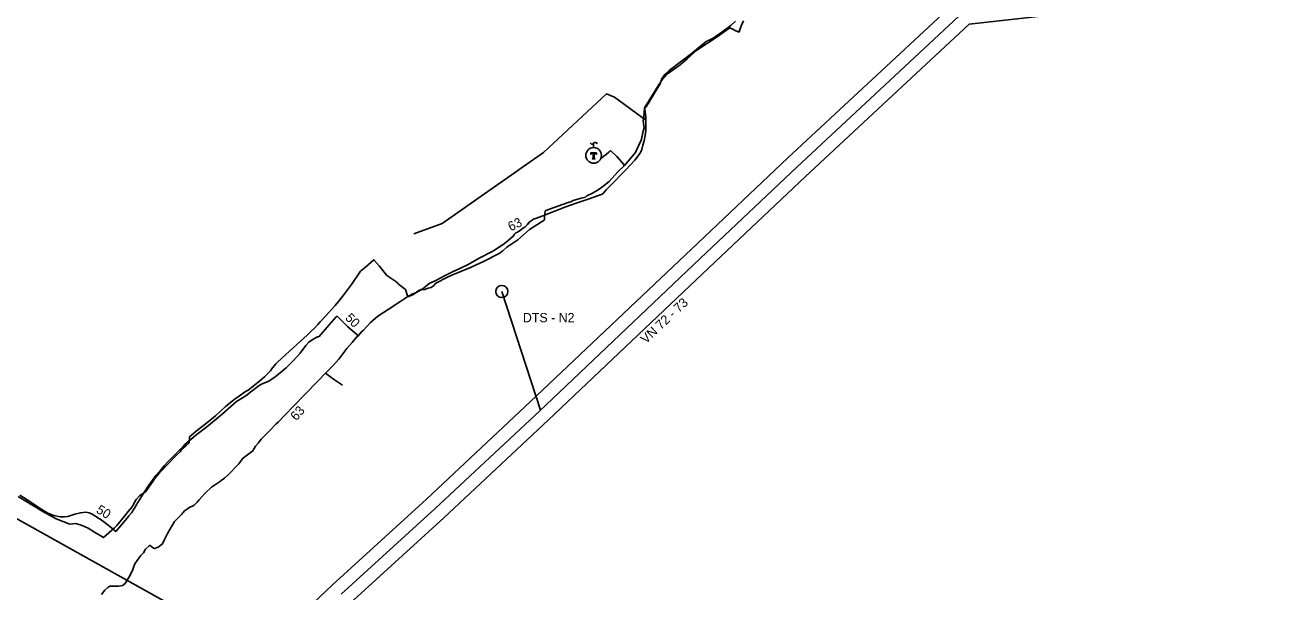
# Model space of a CAD drawing. Extents: x -545241 to -532622, y -1042837 to -1037240.
# Drawn here: x -543496 to -542416, y -1040596 to -1040106 of the extents above; entities that cross this region are included whole.
import ezdxf

# ---------------------------------------------------------------- set-up
doc = ezdxf.new("R2010")
doc.units = 0
for name, color, linetype in [('Vrstva 11', 7, 'Continuous'), ('Vrstva 16', 7, 'Continuous'), ('Vrstva 18', 7, 'Continuous'), ('Vrstva 29', 7, 'Continuous'), ('Vrstva 33', 7, 'Continuous'), ('Vrstva 35', 7, 'Continuous'), ('Vrstva 38', 7, 'Continuous'), ('Vrstva 57', 7, 'Continuous'), ('Vrstva 58', 7, 'Continuous'), ('Vrstva 59', 7, 'Continuous'), ('Vrstva 6', 7, 'Continuous')]:
    doc.layers.add(name, color=color, linetype=linetype)

# ---------------------------------------------------------------- blocks, each defined once
blk = doc.blocks.new('ETRAFN')
at = {"layer": 'Vrstva 6'}
blk.add_circle((0, 0), 7.5, dxfattribs=at)

msp = doc.modelspace()

# ---------------------------------------------------------------- linework, layer by layer
at = {"layer": 'Vrstva 11'}
msp.add_line((-543050.7, -1040438.8), (-543084.2, -1040336.3), dxfattribs=at)
at = {"layer": 'Vrstva 18'}
for points in [[(-542882.4, -1040102.9), (-542886.4, -1040106.6), (-542894.1, -1040112.3), (-542901.6, -1040117.6), (-542905.2, -1040119.3), (-542907.6, -1040120.2), (-542914, -1040125.4), (-542920.6, -1040131.1), (-542929.1, -1040137.3), (-542939.7, -1040145.3), (-542943.4, -1040148.8), (-542946.2, -1040152.9), (-542947.2, -1040156.2), (-542948, -1040157.9), (-542951.1, -1040162.9), (-542954.1, -1040167.9), (-542955.5, -1040170.2), (-542957.5, -1040173.6), (-542957.6, -1040173.7), (-542957.7, -1040173.9), (-542959.8, -1040177), (-542960.6, -1040178), (-542960.6, -1040178.6), (-542960.7, -1040179.1), (-542959.8, -1040185.4), (-542959.9, -1040197.5), (-542960.4, -1040201.5), (-542961.4, -1040206), (-542962.4, -1040209.9), (-542963.3, -1040213.5), (-542964.6, -1040216.9), (-542969.4, -1040222.7), (-542977.1, -1040231.2), (-542977.3, -1040231.4)], [(-542977.3, -1040231.4), (-542978.4, -1040232.5), (-542980.3, -1040234.4), (-542987.6, -1040241.8), (-542994.2, -1040248.5), (-542997.1, -1040251.8), (-542998.2, -1040252.4), (-543001.7, -1040253.7), (-543008.8, -1040256.2), (-543011.3, -1040257.2), (-543019.9, -1040260.1), (-543029.8, -1040263.3), (-543038.4, -1040266.9), (-543041.5, -1040267.9), (-543047.8, -1040270.6), (-543055.2, -1040273.2), (-543056.6, -1040273.5), (-543058, -1040274.6), (-543060.5, -1040276.5), (-543062.1, -1040278.5), (-543064.3, -1040280.7), (-543065, -1040281.1), (-543066.2, -1040281.9), (-543067.4, -1040282.8), (-543067.6, -1040282.9), (-543069.8, -1040284.5), (-543070.7, -1040284.9), (-543072.2, -1040285.7), (-543073.2, -1040286.8), (-543074.3, -1040288.5), (-543079.1, -1040292.4), (-543082.9, -1040295.7), (-543092, -1040301.5), (-543103.2, -1040307.3), (-543113.9, -1040313.3), (-543124.9, -1040318.4), (-543125, -1040318.5), (-543133, -1040322.4), (-543141.8, -1040327), (-543146.3, -1040329.1), (-543148.3, -1040330.4), (-543152.3, -1040333.9), (-543155.8, -1040335.9), (-543156.6, -1040336.4), (-543157.8, -1040337.2), (-543159.4, -1040337.7), (-543161.8, -1040338.7), (-543161.8, -1040338.7), (-543163.6, -1040339.6), (-543165.2, -1040340.5), (-543172.3, -1040345.1), (-543182.4, -1040351.7), (-543191.2, -1040357.6), (-543197.5, -1040363.1), (-543203.7, -1040369.6), (-543205, -1040370.8), (-543206.9, -1040372.8), (-543206.9, -1040372.9), (-543208.1, -1040374.6)], [(-543208.1, -1040374.6), (-543208.5, -1040374.2), (-543209.1, -1040373.9), (-543209.2, -1040373.8), (-543217.4, -1040366.5), (-543217.7, -1040366.2), (-543218, -1040366), (-543226.1, -1040357.9), (-543226.2, -1040357.8), (-543226.3, -1040357.7), (-543226.4, -1040357.7), (-543227.1, -1040358.2), (-543233.2, -1040365.1), (-543242.3, -1040375.5), (-543243.4, -1040375.4), (-543247.2, -1040377.5), (-543250.8, -1040380), (-543253.3, -1040383), (-543258.2, -1040389.4), (-543264.4, -1040396.2), (-543270.5, -1040402.1), (-543275.5, -1040406.6), (-543279.9, -1040410), (-543285.4, -1040413.7), (-543291.6, -1040416.4), (-543293.6, -1040417.5), (-543302, -1040423.8), (-543304.5, -1040425.8), (-543313.3, -1040431.4), (-543325.4, -1040441.9), (-543337.5, -1040452), (-543348.7, -1040460.7), (-543357.8, -1040468.5), (-543359.3, -1040470), (-543372.6, -1040483.4), (-543375.7, -1040486.8), (-543379.2, -1040491.1), (-543383.3, -1040495.6), (-543386.4, -1040500), (-543388.4, -1040502.8), (-543392.7, -1040509.3), (-543393.8, -1040511.1), (-543394.3, -1040512), (-543394.7, -1040512.5), (-543395.2, -1040513.3), (-543400.2, -1040521.3), (-543400.3, -1040521.5), (-543401.5, -1040523.5), (-543403.9, -1040527.3), (-543406.3, -1040530.1), (-543407.7, -1040531.9), (-543417.5, -1040543.6), (-543422.6, -1040539.2), (-543425.4, -1040536.8), (-543430, -1040533.4), (-543434.7, -1040530.5), (-543437.8, -1040528.7), (-543440.4, -1040527.5), (-543443.5, -1040526.9), (-543448.1, -1040527.4), (-543452.8, -1040528.7), (-543455.4, -1040529.5), (-543458.9, -1040530.5), (-543461.8, -1040530.9), (-543465.5, -1040531), (-543471, -1040529.6), (-543476.3, -1040527.6), (-543482.8, -1040523.7), (-543490.9, -1040518.3), (-543500.4, -1040512.1)], [(-543208.1, -1040374.6), (-543208.4, -1040375.1), (-543208.6, -1040375.2), (-543209.3, -1040375.3), (-543209.8, -1040375.8), (-543213.3, -1040380.4), (-543217.9, -1040385.5), (-543219.8, -1040387.8), (-543224.9, -1040394.7), (-543230.5, -1040400.7), (-543236.4, -1040406.7), (-543242.8, -1040413.5), (-543254.8, -1040425.8), (-543271.6, -1040443.2), (-543277.3, -1040449), (-543278.9, -1040450.6), (-543284.5, -1040456.4), (-543285, -1040457), (-543291.9, -1040463.9), (-543294.6, -1040467.2), (-543296.9, -1040469.8), (-543298.1, -1040471.8), (-543299.4, -1040474.2), (-543300.2, -1040474.8), (-543307.3, -1040479.8), (-543307.4, -1040479.9), (-543311.3, -1040485.2), (-543320.1, -1040494.2), (-543323.6, -1040497.6), (-543326.6, -1040499.6), (-543327.2, -1040500), (-543335, -1040505.3), (-543340.3, -1040510.4), (-543345.6, -1040516.1), (-543347.5, -1040518.5), (-543349.9, -1040520.7), (-543350.7, -1040521.5), (-543351.2, -1040521.6), (-543351.2, -1040521.6), (-543352.9, -1040522.3), (-543353.5, -1040522.6), (-543355.6, -1040523.9), (-543358.2, -1040525.8), (-543360.8, -1040528.9), (-543362.4, -1040530.6), (-543366.7, -1040535), (-543372.8, -1040545.4), (-543375.4, -1040550.4), (-543377.1, -1040554.1), (-543380.8, -1040557.1), (-543384, -1040558.3), (-543385, -1040558), (-543387.8, -1040555.6), (-543388.2, -1040555.5), (-543388.8, -1040555.9), (-543391.8, -1040558.8), (-543393.7, -1040561.9), (-543394, -1040562.2), (-543396.1, -1040564.6), (-543396.2, -1040564.7), (-543399.1, -1040568.6), (-543401.2, -1040571.4), (-543402, -1040573.7), (-543403.1, -1040577.3), (-543405.9, -1040582.6), (-543409.3, -1040588.4), (-543410.5, -1040589.3), (-543411, -1040589.7), (-543411.7, -1040590.2), (-543415.2, -1040590.7), (-543418.4, -1040590.9), (-543422.7, -1040590.8), (-543424.4, -1040592), (-543426.9, -1040594.3), (-543429.9, -1040598)], [(-543236.4, -1040406.7), (-543229.5, -1040411.9), (-543221.8, -1040417.1)]]:
    msp.add_lwpolyline(points, dxfattribs=at)
at = {"layer": 'Vrstva 33'}
for points in [[(-543215.4, -1040605.8), (-543134.2, -1040531.6), (-543044.2, -1040447.5), (-542905.4, -1040315.7), (-542822, -1040236.9), (-542680.6, -1040105.3), (-542572.1, -1040093.3), (-542432.8, -1040080.8), (-542229.9, -1040058.3), (-542111, -1040051.2), (-541878.9, -1039938), (-541766.7, -1039884.9)], [(-542699.6, -1040093), (-542837.1, -1040220.9), (-542920.5, -1040299.7), (-543059.3, -1040431.4), (-543149.1, -1040515.5), (-543230.4, -1040589.7), (-543402.9, -1040753.1), (-543445.3, -1040766.3)]]:
    msp.add_lwpolyline(points, dxfattribs=at)
at = {"layer": 'Vrstva 35'}
msp.add_lwpolyline([(-542959.7, -1040188.3), (-542987, -1040168.4), (-542993.8, -1040165.6), (-543048.3, -1040216.1), (-543135.7, -1040277.5), (-543160.2, -1040286.6)], dxfattribs=at)
at = {"layer": 'Vrstva 38'}
msp.add_lwpolyline([(-541771.3, -1039874.9), (-541883.7, -1039928.1), (-542113.9, -1040040.3), (-542230.8, -1040047.3), (-542433.9, -1040069.9), (-542573.2, -1040082.4), (-542685.4, -1040094.8), (-542829.5, -1040228.9), (-542913, -1040307.7), (-543051.7, -1040439.5), (-543141.7, -1040523.6), (-543222.9, -1040597.8)], dxfattribs=at)
at = {"layer": 'Vrstva 57'}
for p, q in [((-543004.9, -1040208.2), (-543004.9, -1040212)), ((-543007, -1040217.5), (-543007.4, -1040217.2)), ((-543006.7, -1040217.2), (-543007.3, -1040216.6)), ((-543006.3, -1040216.8), (-543006.7, -1040216.5)), ((-543005.6, -1040216.8), (-543005.9, -1040216.5)), ((-543005.7, -1040221.7), (-543005.9, -1040221.5)), ((-543005, -1040221.7), (-543005.5, -1040221.2)), ((-543004.5, -1040217.3), (-543005.2, -1040216.5)), ((-543004.5, -1040218), (-543005.2, -1040217.2)), ((-543004.5, -1040218.7), (-543005.2, -1040217.9)), ((-543004.5, -1040219.4), (-543005.2, -1040218.6)), ((-543004.5, -1040220.1), (-543005.2, -1040219.4)), ((-543004.5, -1040220.8), (-543005.2, -1040220.1)), ((-543004.2, -1040221.7), (-543005.2, -1040220.8)), ((-543004.2, -1040216.8), (-543004.5, -1040216.5)), ((-543003.5, -1040216.8), (-543003.8, -1040216.5)), ((-543002.3, -1040217.3), (-543003.1, -1040216.5)), ((-543002.4, -1040216.5), (-543002.5, -1040216.4))]:
    msp.add_line(p, q, dxfattribs=at)
msp.add_lwpolyline([(-543007.8, -1040207.8), (-543007.3, -1040208.4), (-543006.7, -1040208.9), (-543006.3, -1040209), (-543005.9, -1040209), (-543005.4, -1040208.7), (-543004.9, -1040208.2), (-543004.5, -1040207.8), (-543004, -1040207.5), (-543003.6, -1040207.4), (-543003.2, -1040207.5), (-543002.5, -1040208), (-543002, -1040208.7)], dxfattribs=at)
msp.add_lwpolyline([(-543002.4, -1040216.4), (-543002.3, -1040217.8), (-543002.5, -1040217.8), (-543003.3, -1040216.8), (-543004.5, -1040216.8), (-543004.5, -1040220.9), (-543003.7, -1040221.6), (-543003.7, -1040221.7), (-543006, -1040221.7), (-543006, -1040221.6), (-543005.2, -1040220.9), (-543005.2, -1040216.8), (-543006.3, -1040216.8), (-543007.2, -1040217.8), (-543007.4, -1040217.8), (-543007.3, -1040216.4), (-543007.1, -1040216.4), (-543006.8, -1040216.5), (-543002.9, -1040216.5), (-543002.6, -1040216.4)], close=True, dxfattribs=at)
msp.add_circle((-543004.9, -1040218.7), 6.75, dxfattribs=at)
at = {"layer": 'Vrstva 58'}
for points in [[(-542875.6, -1040102.6), (-542877.3, -1040106.3), (-542879.1, -1040111.6), (-542878.9, -1040111.9), (-542880.2, -1040112.1), (-542883.3, -1040110.5), (-542884.2, -1040110), (-542887.3, -1040108.6), (-542888.5, -1040109.4), (-542889.8, -1040110.4), (-542897.4, -1040115.8), (-542915.8, -1040127.8), (-542924.1, -1040135.2), (-542930.3, -1040140.5), (-542942.1, -1040148.8), (-542945.5, -1040152.9), (-542948, -1040156.8), (-542948.3, -1040157.3), (-542951.5, -1040162.3), (-542956.7, -1040170.8), (-542961.1, -1040177.7), (-542961.7, -1040185.9), (-542962.2, -1040188.7), (-542961.8, -1040191.3), (-542961.2, -1040195), (-542962.4, -1040198.9), (-542963.1, -1040202.1), (-542963.2, -1040202.7), (-542963.4, -1040203.4), (-542963.8, -1040205.6), (-542968.2, -1040214.7), (-542968.8, -1040216.1), (-542978.2, -1040227.3)], [(-542978.2, -1040227.3), (-542978.7, -1040227.3), (-542978.8, -1040226.8), (-542979.2, -1040226.3), (-542980.8, -1040224.4), (-542985, -1040219.6), (-542990.1, -1040214.7), (-542990.5, -1040214.9), (-542991.9, -1040216), (-542993.8, -1040217.6), (-542998.7, -1040221.4)], [(-542978.2, -1040227.3), (-542983.9, -1040232.8), (-542991.6, -1040241.3), (-542996.9, -1040245.6), (-543001, -1040248.5), (-543005.8, -1040251.2), (-543010.7, -1040253.5), (-543011.8, -1040254.7), (-543015.7, -1040255.6), (-543022.6, -1040257.6), (-543024.7, -1040258.9), (-543025.9, -1040259.2), (-543031.7, -1040261), (-543046.2, -1040266.3), (-543046.8, -1040266.8), (-543047.3, -1040271.5), (-543047.3, -1040273), (-543047.3, -1040274.3), (-543047.5, -1040274.7), (-543060.2, -1040282.8), (-543070.3, -1040291.5), (-543079.9, -1040298.1), (-543082.9, -1040300.8), (-543083.2, -1040301.1), (-543083.5, -1040301.3), (-543084.2, -1040301.8), (-543086.4, -1040303.3), (-543099.4, -1040310), (-543111.1, -1040315.5), (-543117.7, -1040318.1), (-543127.3, -1040322.1), (-543131, -1040323.9), (-543141.2, -1040329.2), (-543143.3, -1040331.4), (-543145.1, -1040332.7), (-543147.7, -1040333.3), (-543149.3, -1040334), (-543150.6, -1040334.5), (-543153.7, -1040334.4), (-543155.8, -1040335.4), (-543161, -1040339.2), (-543165.3, -1040340.8), (-543167.4, -1040334.6), (-543173.4, -1040329.8), (-543173.7, -1040329.4), (-543175.1, -1040328.1), (-543175.8, -1040327.5), (-543183.6, -1040322.3), (-543190, -1040314.1), (-543194.7, -1040308.8), (-543202, -1040315.2), (-543206.1, -1040318.8), (-543214, -1040330.2), (-543220.1, -1040338.4), (-543224.1, -1040343.4), (-543228.1, -1040348.3), (-543236.5, -1040357.6), (-543241, -1040362.5), (-543243.1, -1040364.8), (-543246, -1040367.8), (-543248.7, -1040370.4), (-543249.4, -1040371.1), (-543252.2, -1040373.9), (-543258.1, -1040379.2), (-543271, -1040391), (-543278, -1040397.3), (-543279.3, -1040398.8), (-543283.2, -1040403.2), (-543284, -1040404.7), (-543289, -1040410.1), (-543294.9, -1040414.8), (-543303.1, -1040421.6), (-543305.5, -1040422.7), (-543310.6, -1040426.5), (-543314.4, -1040429.1), (-543322.8, -1040435.7), (-543331.5, -1040443.6), (-543339.1, -1040449.9), (-543348.2, -1040456.8), (-543353.8, -1040461.8), (-543354.3, -1040466.9), (-543356.9, -1040469.5), (-543358.9, -1040470.9), (-543360.7, -1040472.6), (-543361.6, -1040474.4), (-543365.9, -1040478.5), (-543372.3, -1040485), (-543379.8, -1040493), (-543384, -1040498.1), (-543385.6, -1040500.4), (-543391.9, -1040509.3), (-543393.5, -1040510.4), (-543396.8, -1040512.5), (-543399.8, -1040516), (-543402.7, -1040521.1), (-543403.5, -1040522.2), (-543406.8, -1040526.4)], [(-543406.8, -1040526.4), (-543410.1, -1040530.4), (-543416.7, -1040538.3), (-543418.2, -1040540), (-543418.5, -1040540.5), (-543428, -1040548.8), (-543436, -1040544), (-543441.4, -1040540.6), (-543446.6, -1040538.4), (-543452, -1040536.5), (-543457.2, -1040537.2), (-543469, -1040532.5), (-543480.4, -1040526.3), (-543489.9, -1040520.6), (-543501.7, -1040513.3)]]:
    msp.add_lwpolyline(points, dxfattribs=at)
at = {"layer": 'Vrstva 59'}
msp.add_lwpolyline([(-545240.6, -1039561.7), (-540702.1, -1042097)], dxfattribs=at)

# ---------------------------------------------------------------- block references
at = {"layer": 'Vrstva 29', "xscale": 0.7, "yscale": 0.7}
msp.add_blockref('ETRAFN', (-543084.2, -1040336.3), dxfattribs=at)

# ---------------------------------------------------------------- texts
at = {"layer": 'Vrstva 16'}
for s, rotation, p in [('63', 26.131, (-543076.5, -1040284.4)), ('50', 315, (-543220, -1040359.7)), ('63', 48.5179, (-543261.6, -1040448.4)), ('50', 328.714, (-543435.1, -1040526.8))]:
    msp.add_text(s, height=8, rotation=rotation, dxfattribs=at).set_placement(p)
at = {"layer": 'Vrstva 59'}
msp.add_text('VN 72 - 73', height=8, rotation=43.3734, dxfattribs=at).set_placement((-542959.8, -1040381.9))
msp.add_text('DTS - N2', height=8, dxfattribs=at).set_placement((-543066, -1040362.8))

doc.saveas('drawing.dxf')
